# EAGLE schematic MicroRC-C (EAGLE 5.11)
BOM: EXCLUDE; CHECKED: K.OLINGER; DATABASE: ./BOM/MicroRC-PARTSDB.txt; DATE: 10/10/06; DRAWN: R.STARR; DRGNO: ED-3XX-01; PARTNO: *; PARTNUM: MF-SM030-2; REV: C

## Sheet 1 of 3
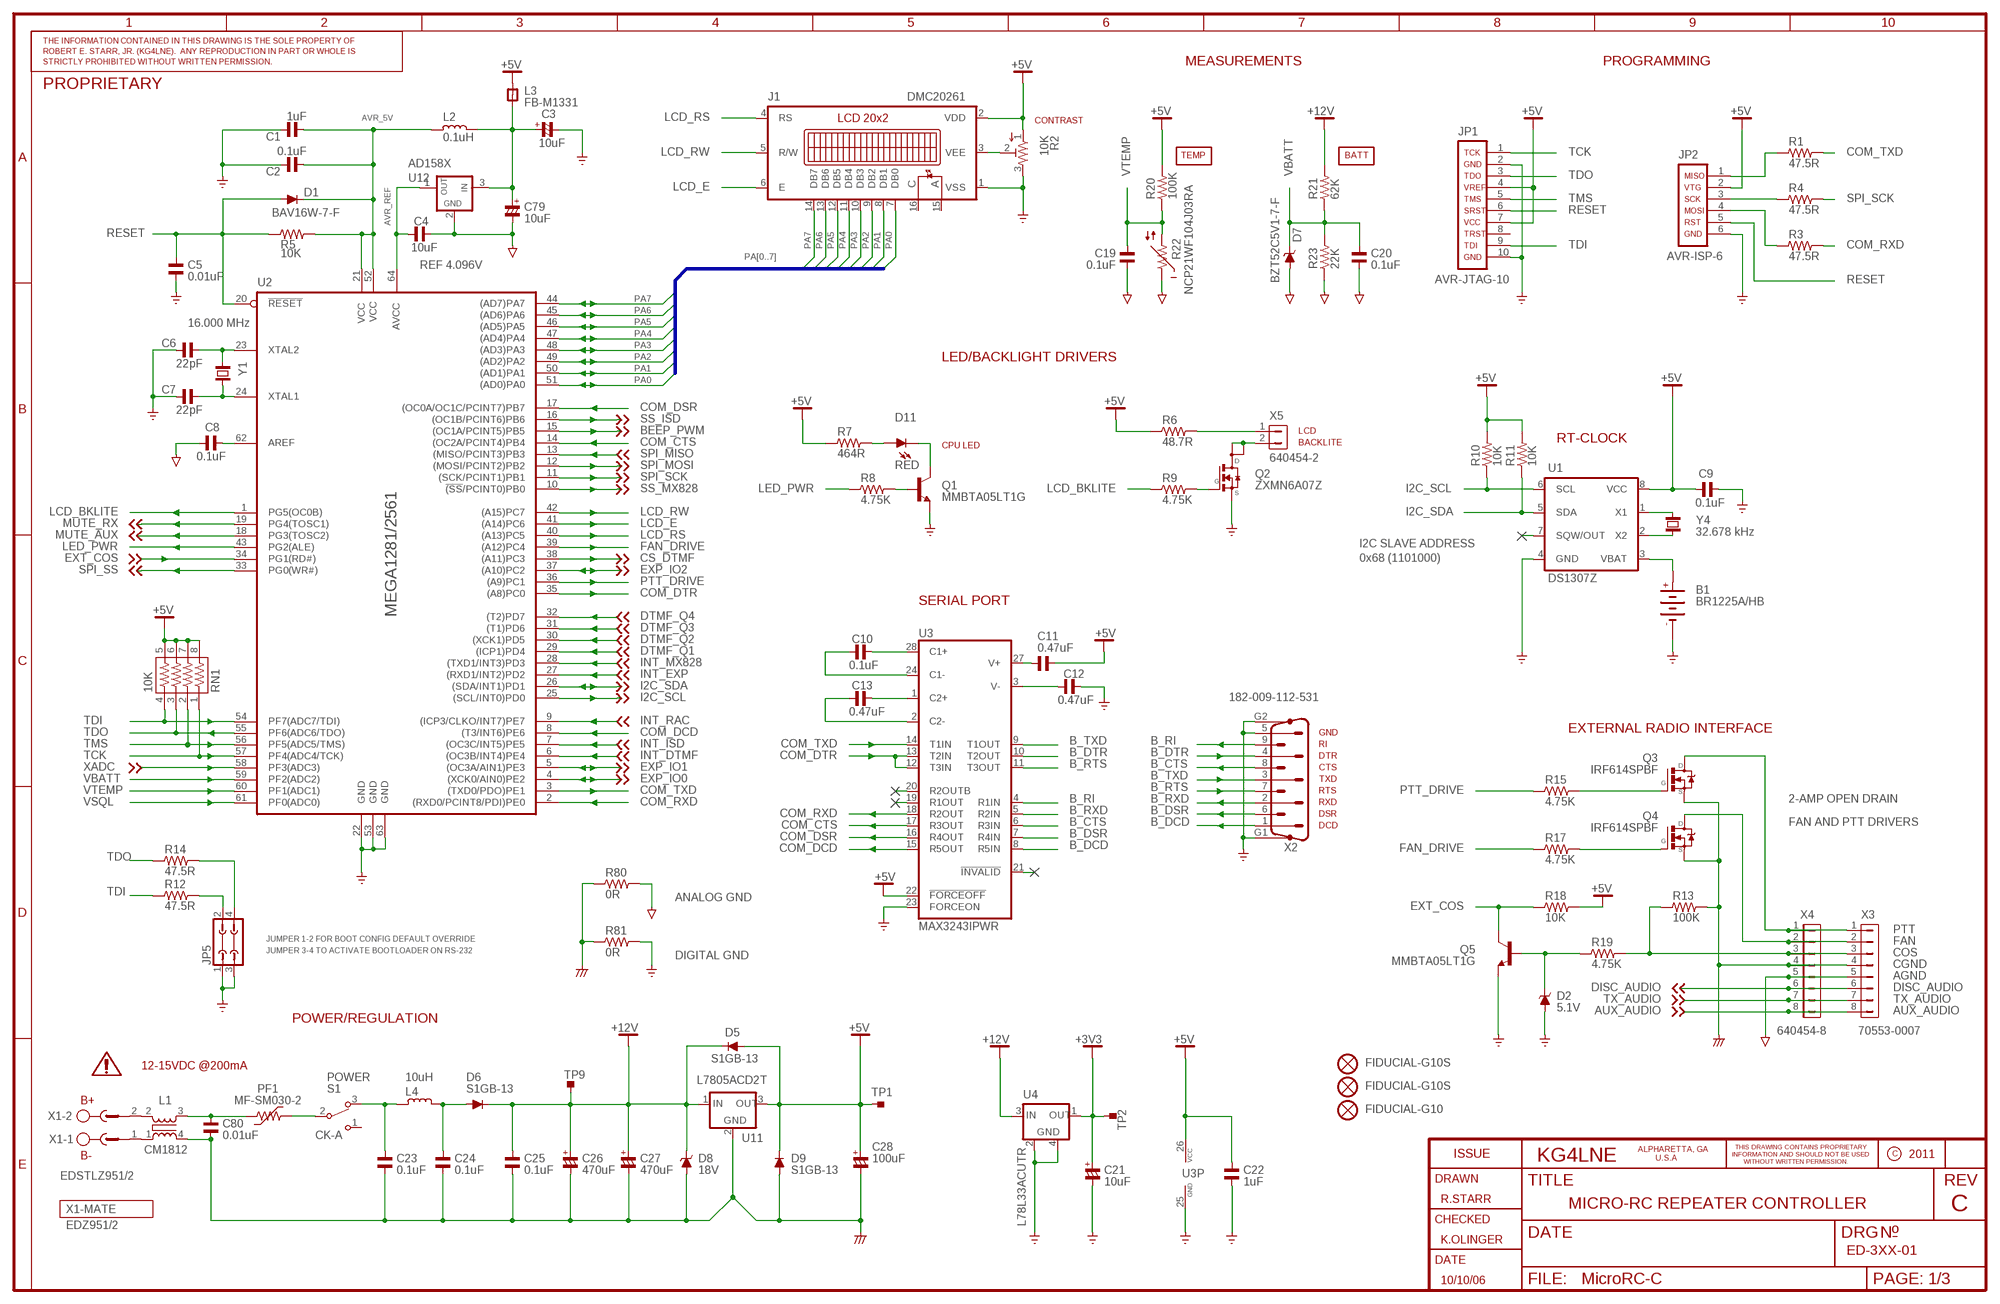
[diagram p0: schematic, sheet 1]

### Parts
B1  BR1225A/HB  BR1225  [BR1225]
C1  1uF  C_0805  [C0805]
C2  0.1uF  C_0805  [C0805]
C3  10uF  CP_3528  [C3528/T]
C4  10uF  C_0805  [C0805]
C5  0.01uF  C_0805  [C0805]
C6  22pF  C_0805  [C0805]
C7  22pF  C_0805  [C0805]
C8  0.1uF  C_0805  [C0805]
C9  0.1uF  C_0805  [C0805]
C10  0.1uF  C_0805  [C0805]
C11  0.47uF  C_0805  [C0805]
C12  0.47uF  C_0805  [C0805]
C13  0.47uF  C_0805  [C0805]
C19  0.1uF  C_0805  [C0805]
C20  0.1uF  C_0805  [C0805]
C21  10uF  CP_3528  [C3528/T]
C22  1uF  C_0805  [C0805]
C23  0.1uF  C_1206  [C1206]
C24  0.1uF  C_1206  [C1206]
C25  0.1uF  C_1206  [C1206]
C26  470uF  CP_SV-G  [CSV-G]
C27  470uF  CP_SV-G  [CSV-G]
C28  100uF  CP_SV-E/F  [CSV-E/F]
C79  10uF  CP_3528  [C3528/T]
C80  0.01uF  C_1206  [C1206]
D1  BAV16W-7-F  DIODE-SOD123  [SOD123]
D2  5.1V  ZENER-DIODESOD123  [SOD123]
D5  S1GB-13  [SMB]
D6  S1GB-13  [SMB]
D7  BZT52C5V1-7-F  ZENER-DIODESOD123  [SOD123]
D8  18V  ZENER-DIODESMB  [SMB]
D9  S1GB-13  [SMB]
D11  RED  LED535XX  [LED535]
FIDUCIAL1  FIDUCIAL-G10S  [G10S]
FIDUCIAL2  FIDUCIAL-G10S  [G10S]
FIDUCIAL3  FIDUCIAL-G10  [G10]
J1  DMC20261  [DMC20261]
JP1  AVR-JTAG-10  [AVR-JTAG-10]
JP2  AVR-ISP-6  [AVR-ISP-6]
JP5  JP2Q  [JP2Q]
L1  CM1812  [CM1812]
L2  0.1uH  L_1206  [L1206]
L3  FB-M1331  FB_1206  [L1206]
L4  10uH  L-PM3308  [PM-13]
PF1  MF-SM030-2  POLYSWITCH-SMD-7555  [SMD-7555]
Q1  MMBTA05LT1G  MMBTA05  [SOT23]
Q2  ZXMN6A07Z  [SOT89]
Q3  IRF614SPBF  IRF614  [D2PAK]
Q4  IRF614SPBF  IRF614  [D2PAK]
Q5  MMBTA05LT1G  MMBTA05  [SOT23]
R1  47.5R  R_0805  [R0805]
R2  10K  TRIM_EU-EVM-L4G  [EVM-L4G]
R3  47.5R  R_0805  [R0805]
R4  47.5R  R_0805  [R0805]
R5  10K  R_0805  [R0805]
R6  48.7R  R_2010  [R2010]
R7  464R  R_1210  [R1210]
R8  4.75K  R_0805  [R0805]
R9  4.75K  R_0805  [R0805]
R10  10K  R_0805  [R0805]
R11  10K  R_0805  [R0805]
R12  47.5R  R_0805  [R0805]
R13  100K  R_0805  [R0805]
R14  47.5R  R_0805  [R0805]
R15  4.75K  R_0805  [R0805]
R17  4.75K  R_0805  [R0805]
R18  10K  R_0805  [R0805]
R19  4.75K  R_0805  [R0805]
R20  100K  R_0805  [R0805]
R21  62K  R_0805  [R0805]
R22  NCP21WF104J03RA  NCP-0805  [R0805]
R23  22K  R_0805  [R0805]
R80  0R  R_0805  [R0805]
R81  0R  R_0805  [R0805]
RN1  10K  744-8  [744-8]
S1  CK-A  [CK-A]
TP1  TPTP10SQ  [TP10SQ]
TP2  TPTP10SQ  [TP10SQ]
TP9  TPTP10SQ  [TP10SQ]
U1  DS1307Z  [SO08]
U2  MEGA1281/2561  [TQFP64-AEB]
U3  MAX3243IPWR  MAX3243PW  [TSSOP28]
U4  L78L33ACUTR  L78LXXCU/BU  [SOT89-4]
U11  L7805ACD2T  L78XXD2T  [D2PAK]
U12  AD158X  [SOT23]
X1  EDSTLZ951/2  EDSTLZ-2-951  [951-2]
X2  182-009-112-531  NC182M9-VS  [NC182M9]
X3  70553-0007  HDR-1X8-70553-?  [70553-08]
X4  640454-8  MTA08-100  [MTA08-100]
X5  640454-2  HDR-1X2-MTA-100  [MTA-100-2V]
Y1  16.000 MHz  CRYTALTC38H  [TC38H]
Y4  32.678 kHz  CRYTALTC26H  [TC26H]

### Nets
+3V3: C21.+ TP2.TP U4.1(OUT) ; also sheet 2
+5V: C9.1 C11.1 C22.1 C28.+ D5.A D9.C J1.2(VDD) JP1.4 JP1.7 JP2.2 L3.2 R2.1 R6.1 R7.1 R10.2 R11.2 R18.2 R20.2 RN1.5 RN1.6 RN1.7 RN1.8 TP1.TP U1.8(VCC) U3.22(!FORCEOFF!) U3.26(VCC) U11.3(OUT) ; also sheet 2
+12V: C25.1 C26.+ C27.+ D5.C D6.C D8.C R21.2 TP9.TP U4.3(IN) U11.1(IN) ; also sheet 2
AGND: C4.1 C8.2 C19.2 C20.2 C79.- D7.A R22.1 R23.1 R80.2 U12.2(GND) X3.5 X4.5 ; supply symbol labelled AGND_ ; also sheet 2
AUX_AUDIO: X3.8 X4.8 ; also sheet 2
AVR_5V: C1.1 C2.1 D1.C L2.2 R5.2 U2.21(VCC) U2.52(VCC1)
AVR_REF: C4.2 U2.64(AVCC) U12.1(OUT)
B_CTS: U3.6(R3IN) X2.8
B_DCD: U3.8(R5IN) X2.1
B_DSR: U3.7(R4IN) X2.6
B_DTR: U3.10(T2OUT) X2.4
B_RI: U3.4(R1IN) X2.9
B_RTS: U3.11(T3OUT) X2.7
B_RXD: U3.5(R2IN) X2.2
B_TXD: U3.9(T1OUT) X2.3
BEEP_PWM: U2.15((OC1A/PCINT5)PB5) ; also sheet 2
CGND: C23.2 C24.2 C25.2 C26.- C27.- C28.- C80.2 D8.A D9.A L1.4 Q3.3(S) Q4.3(S) R13.2 R80.1 R81.1 U11.2(GND) X3.4 X4.4 ; supply symbol labelled CGND_
COM_CTS: U2.14((OC2A/PCINT4)PB4) U3.17(R3OUT)
COM_DCD: U2.8((T3/INT6)PE6) U3.15(R5OUT)
COM_DSR: U2.17((OC0A/OC1C/PCINT7)PB7) U3.16(R4OUT)
COM_DTR: U2.35((A8)PC0) U3.12(T3IN) U3.13(T2IN)
COM_RXD: R3.2 U2.2((RXD0/PCINT8/PDI)PE0) U3.18(R2OUT)
COM_TXD: R1.2 U2.3((TXD0/PDO)PE1) U3.14(T1IN)
COS: R13.1 R19.2 X3.3 X4.3
CS_DTMF: U2.38((A11)PC3) ; also sheet 2
DISC_AUDIO: X3.6 X4.6 ; also sheet 2
DTMF_Q1: U2.29((ICP1)PD4) ; also sheet 2
DTMF_Q2: U2.30((XCK1)PD5) ; also sheet 2
DTMF_Q3: U2.31((T1)PD6) ; also sheet 2
DTMF_Q4: U2.32((T2)PD7) ; also sheet 2
EXP_IO0: U2.4((XCK0/AIN0)PE2) ; also sheet 2
EXP_IO1: U2.5((OC3A/AIN1)PE3) ; also sheet 2
EXP_IO2: U2.37((A10)PC2) ; also sheet 2
EXT_COS: Q5.3(C) R18.1 U2.34(PG1(RD#))
FAN: Q4.2(D) X3.2 X4.2
FAN_DRIVE: R17.1 U2.39((A12)PC4)
GND: B1.- C1.2 C2.2 C3.- C5.2 C6.2 C7.2 C9.2 C12.1 C21.- C22.2 D2.A J1.1(VSS) JP1.2 JP1.10 JP2.6 JP5.1 JP5.3 Q1.2(E) Q2.3(S) Q5.2(E) R2.3 R81.2 U1.4(GND) U2.22(GND) U2.53(GND1) U2.63(GND2) U3.23(FORCEON) U3.25(GND) U4.2(GND) U4.4(GND1) X2.5 X2.G1 X2.G2 ; supply symbol labelled GND_ ; also sheet 2
I2C_SCL: R10.1 U1.6(SCL) U2.25((SCL/INT0)PD0) ; also sheet 2
I2C_SDA: R11.1 U1.5(SDA) U2.26((SDA/INT1)PD1) ; also sheet 2
INT_DTMF: U2.6((OC3B/INT4)PE4) ; also sheet 2
INT_EXP: U2.27((RXD1/INT2)PD2) ; also sheet 2
INT_ISD: U2.7((OC3C/INT5)PE5) ; also sheet 2
INT_MX828: U2.28((TXD1/INT3)PD3) ; also sheet 2
INT_RAC: U2.9((ICP3/CLKO/INT7)PE7) ; also sheet 2
LCD_BKLITE: R9.1 U2.1(PG5(OC0B))
LCD_E: J1.6(E) U2.41((A14)PC6)
LCD_RS: J1.4(RS) U2.40((A13)PC5)
LCD_RW: J1.5(R/W) U2.42((A15)PC7)
LED_PWR: R8.1 U2.43(PG2(ALE))
MUTE_AUX: U2.18(PG3(TOSC2)) ; also sheet 2
MUTE_RX: U2.19(PG4(TOSC1)) ; also sheet 2
N$1: L1.1 X1.1
N$2: C8.1 U2.62(AREF)
N$9: JP5.2 R12.2
N$13: C23.1 L4.1 S1.3(O)
N$14: L1.2 X1.2
N$19: C24.1 D6.A L4.2
N$20: U1.1(X1) Y4.2
N$21: U1.2(X2) Y4.1
N$30: C7.1 U2.24(XTAL1) Y1.1
N$31: JP5.4 R14.2
N$34: C12.2 U3.3(V-)
N$36: C11.2 U3.27(V+)
N$38: C6.1 U2.23(XTAL2) Y1.2
N$39: C13.1 U3.1(C2+)
N$44: C10.1 U3.28(C1+)
N$45: C13.2 U3.2(C2-)
N$46: C10.2 U3.24(C1-)
N$63: B1.+ U1.3(VBAT)
N$66: Q3.1(G) R15.2
N$67: Q2.1(G) R9.2
N$68: Q2.2(D) Q2.4(D2) X5.2
N$69: R6.2 X5.1
N$76: D2.C Q5.1(B) R19.1
N$78: PF1.2 S1.2(P)
N$79: Q4.1(G) R17.2
N$81: C80.1 L1.3 PF1.1
N$86: C3.+ C79.+ L2.1 L3.1 U12.3(IN)
N$90: D11.K(C) Q1.3(C)
N$91: D11.A R7.2
N$92: Q1.1(B) R8.2
N$105: JP2.1 R1.1
N$107: JP2.3 R4.1
N$108: JP2.4 R3.1
PA0: J1.7(DB0) U2.51((AD0)PA0)
PA1: J1.8(DB1) U2.50((AD1)PA1)
PA2: J1.9(DB2) U2.49((AD2)PA2)
PA3: J1.10(DB3) U2.48((AD3)PA3)
PA4: J1.11(DB4) U2.47((AD4)PA4)
PA5: J1.12(DB5) U2.46((AD5)PA5)
PA6: J1.13(DB6) U2.45((AD6)PA6)
PA7: J1.14(DB7) U2.44((AD7)PA7)
PTT: Q3.2(D) X3.1 X4.1
PTT_DRIVE: R15.1 U2.36((A9)PC1)
RESET: C5.1 D1.A JP1.6 JP2.5 R5.1 U2.20(!RESET!)
SPI_MISO: U2.13((MISO/PCINT3)PB3) ; also sheet 2
SPI_MOSI: U2.12((MOSI/PCINT2)PB2) ; also sheet 2
SPI_SCK: R4.2 U2.11((SCK/PCINT1)PB1) ; also sheet 2
SPI_SS: U2.33(PG0(WR#)) ; also sheet 2
SS_ISD: U2.16((OC1B/PCINT6)PB6) ; also sheet 2
SS_MX828: U2.10(!(SS!/PCINT0)PB0) ; also sheet 2
TCK: JP1.1 RN1.1 U2.57(PF4(ADC4/TCK))
TDI: JP1.9 R12.1 RN1.4 U2.54(PF7(ADC7/TDI))
TDO: JP1.3 R14.1 RN1.3 U2.55(PF6(ADC6/TDO))
TMS: JP1.5 RN1.2 U2.56(PF5(ADC5/TMS))
TX_AUDIO: X3.7 X4.7 ; also sheet 2
VBATT: C20.1 D7.C R21.1 R23.2 U2.59(PF2(ADC2))
VEE_LCD: J1.3(VEE) R2.2
VSQL: U2.61(PF0(ADC0)) ; also sheet 2
VTEMP: C19.1 R20.1 R22.2 U2.60(PF1(ADC1))
XADC: U2.58(PF3(ADC3)) ; also sheet 2
Unconnected: J1.15(A) J1.16(C) JP1.8 S1.1(S) U1.7(SQW/OUT) U3.19(R1OUT) U3.20(R2OUTB) U3.21(!INVALID!)

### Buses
PA[0..7]

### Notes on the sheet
- MEASUREMENTS | PROGRAMMING
- CONTRAST
- TEMP | BATT
- REF 4.096V
- LED/BACKLIGHT DRIVERS
- LCD
- RT-CLOCK
- BACKLITE
- CPU LED
- I2C SLAVE ADDRESS
- 0x68 (1101000)
- SERIAL PORT
- EXTERNAL RADIO INTERFACE
- GND
- RI
- DTR
- CTS
- TXD
- RTS
- 2-AMP OPEN DRAIN
- RXD
- DSR
- FAN AND PTT DRIVERS
- DCD
- ANALOG GND
- JUMPER 1-2 FOR BOOT CONFIG DEFAULT OVERRIDE
- JUMPER 3-4 TO ACTIVATE BOOTLOADER ON RS-232
- DIGITAL GND
- POWER/REGULATION
- 12-15VDC @200mA
- POWER
- B+
- B-
- MICRO-RC REPEATER CONTROLLER

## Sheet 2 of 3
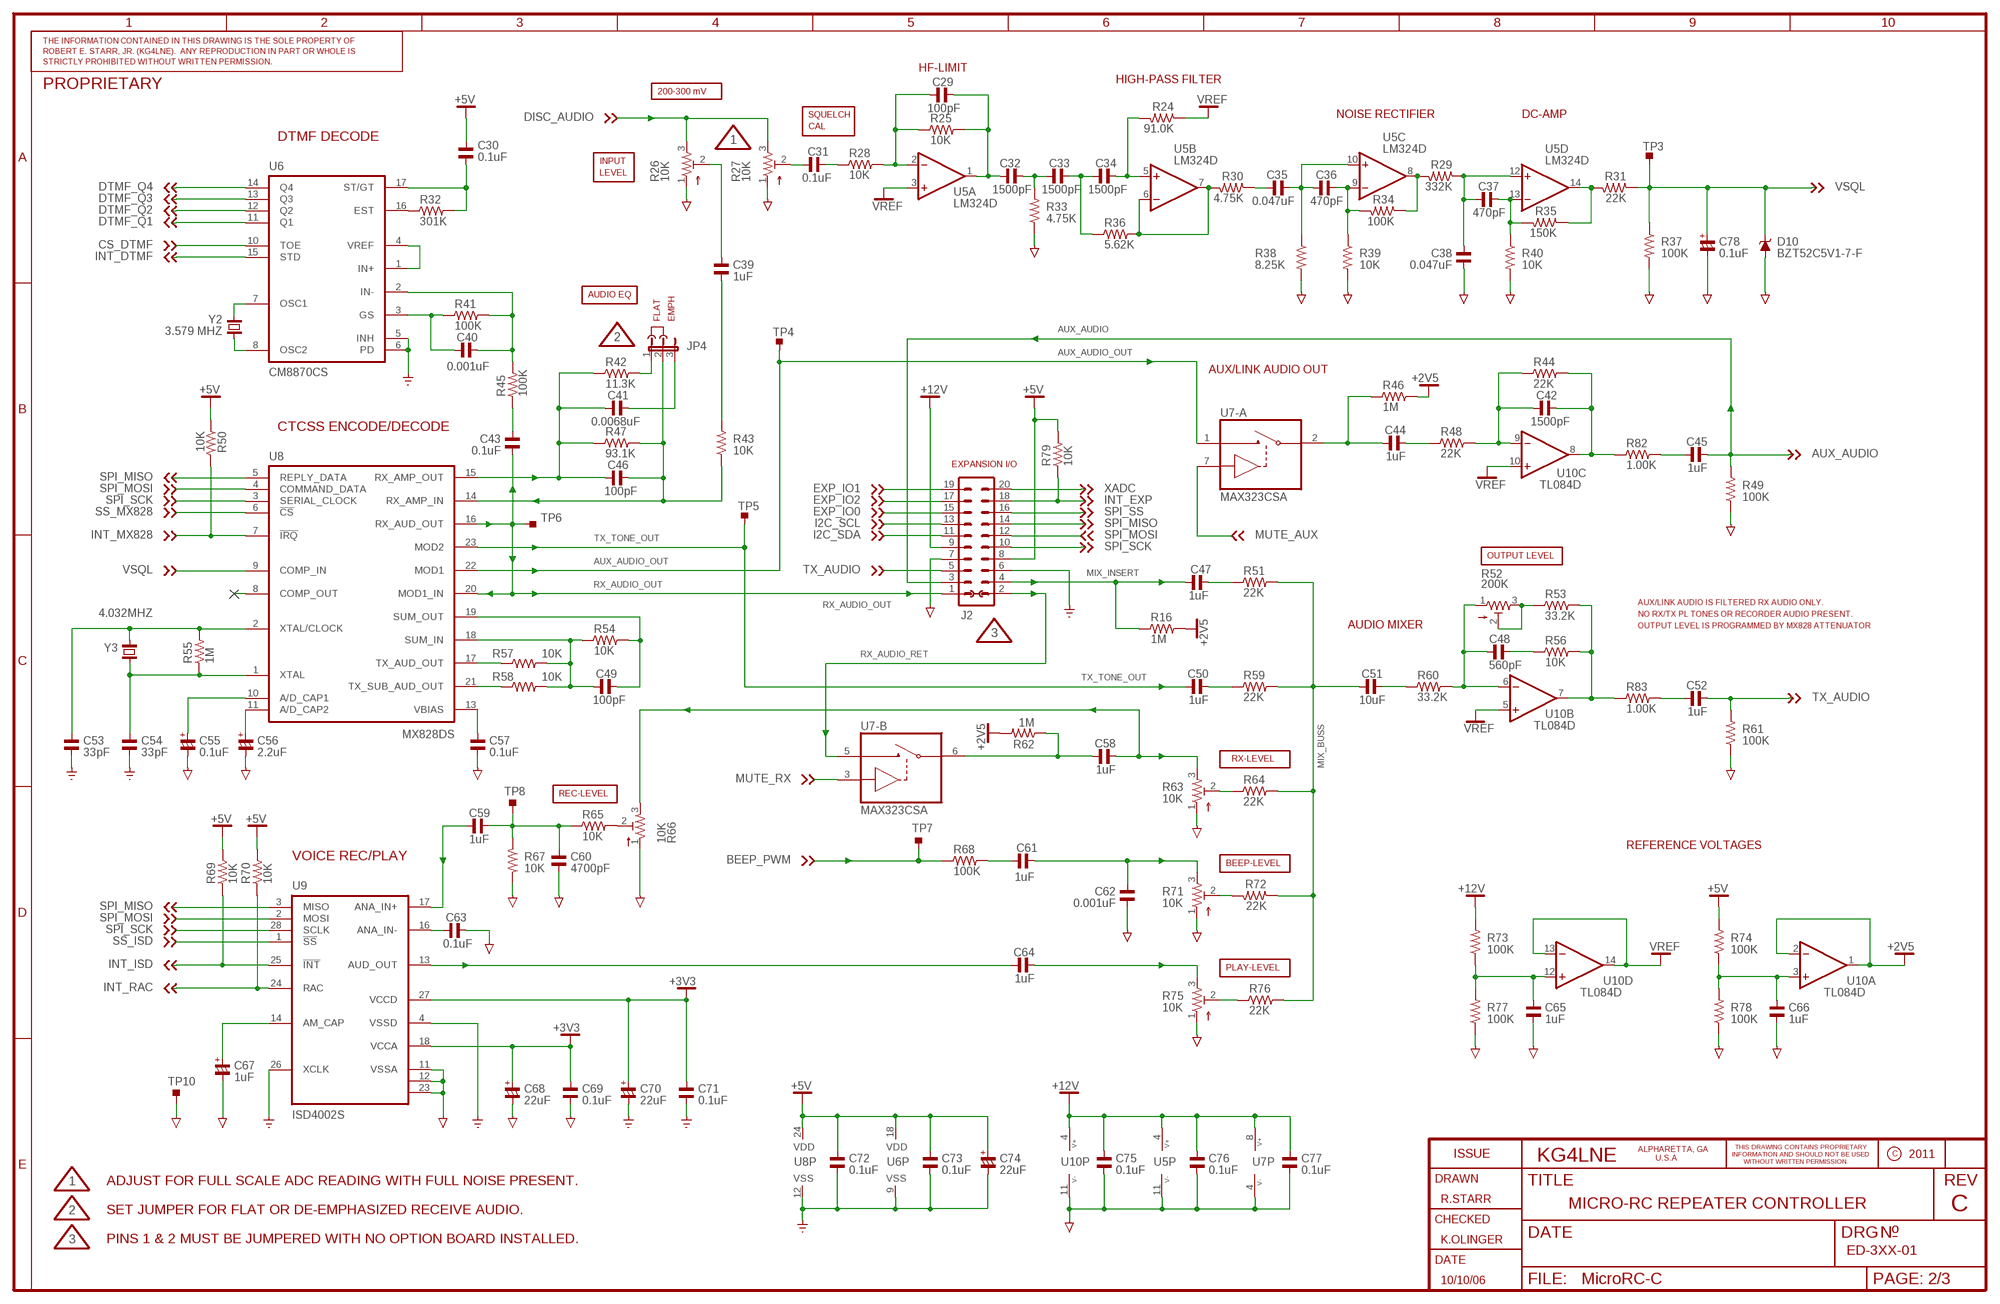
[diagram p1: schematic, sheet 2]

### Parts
C29  100pF  C_0805  [C0805]
C30  0.1uF  C_0805  [C0805]
C31  0.1uF  C_0805  [C0805]
C32  1500pF  C_0805  [C0805]
C33  1500pF  C_0805  [C0805]
C34  1500pF  C_0805  [C0805]
C35  0.047uF  C_0805  [C0805]
C36  470pF  C_0805  [C0805]
C37  470pF  C_0805  [C0805]
C38  0.047uF  C_0805  [C0805]
C39  1uF  C_0805  [C0805]
C40  0.001uF  C_0805  [C0805]
C41  0.0068uF  C_0805  [C0805]
C42  1500pF  C_0805  [C0805]
C43  0.1uF  C_0805  [C0805]
C44  1uF  C_0805  [C0805]
C45  1uF  C_0805  [C0805]
C46  100pF  C_0805  [C0805]
C47  1uF  C_0805  [C0805]
C48  560pF  C_0805  [C0805]
C49  100pF  C_0805  [C0805]
C50  1uF  C_0805  [C0805]
C51  10uF  C_0805  [C0805]
C52  1uF  C_0805  [C0805]
C53  33pF  C_0805  [C0805]
C54  33pF  C_0805  [C0805]
C55  0.1uF  CP_3216  [C3216/T]
C56  2.2uF  CP_3216  [C3216/T]
C57  0.1uF  C_0805  [C0805]
C58  1uF  C_0805  [C0805]
C59  1uF  C_0805  [C0805]
C60  4700pF  C_0805  [C0805]
C61  1uF  C_0805  [C0805]
C62  0.001uF  C_0805  [C0805]
C63  0.1uF  C_0805  [C0805]
C64  1uF  C_0805  [C0805]
C65  1uF  C_0805  [C0805]
C66  1uF  C_0805  [C0805]
C67  1uF  CP_3216  [C3216/T]
C68  22uF  CP_3528  [C3528/T]
C69  0.1uF  C_0805  [C0805]
C70  22uF  CP_3528  [C3528/T]
C71  0.1uF  C_0805  [C0805]
C72  0.1uF  C_0805  [C0805]
C73  0.1uF  C_0805  [C0805]
C74  22uF  CP_3528  [C3528/T]
C75  0.1uF  C_0805  [C0805]
C76  0.1uF  C_0805  [C0805]
C77  0.1uF  C_0805  [C0805]
C78  0.1uF  CP_3216  [C3216/T]
D10  BZT52C5V1-7-F  ZENER-DIODESOD123  [SOD123]
J2  MA10-2  [MA10-2]
JP4  JP2E  [JP2]
R16  1M  R_0805  [R0805]
R24  91.0K  R_0805  [R0805]
R25  10K  R_0805  [R0805]
R26  10K  TRIM_EU-EVME-SIDE  [EVME-SIDE]
R27  10K  TRIM_EU-EVME-SIDE  [EVME-SIDE]
R28  10K  R_0805  [R0805]
R29  332K  R_0805  [R0805]
R30  4.75K  R_0805  [R0805]
R31  22K  R_0805  [R0805]
R32  301K  R_0805  [R0805]
R33  4.75K  R_0805  [R0805]
R34  100K  R_0805  [R0805]
R35  150K  R_0805  [R0805]
R36  5.62K  R_0805  [R0805]
R37  100K  R_0805  [R0805]
R38  8.25K  R_0805  [R0805]
R39  10K  R_0805  [R0805]
R40  10K  R_0805  [R0805]
R41  100K  R_0805  [R0805]
R42  11.3K  R_0805  [R0805]
R43  10K  R_0805  [R0805]
R44  22K  R_0805  [R0805]
R45  100K  R_0805  [R0805]
R46  1M  R_0805  [R0805]
R47  93.1K  R_0805  [R0805]
R48  22K  R_0805  [R0805]
R49  100K  R_0805  [R0805]
R50  10K  R_0805  [R0805]
R51  22K  R_0805  [R0805]
R52  200K  TRIM_EU-EVME-SIDE  [EVME-SIDE]
R53  33.2K  R_0805  [R0805]
R54  10K  R_0805  [R0805]
R55  1M  R_0805  [R0805]
R56  10K  R_0805  [R0805]
R57  10K  R_0805  [R0805]
R58  10K  R_0805  [R0805]
R59  22K  R_0805  [R0805]
R60  33.2K  R_0805  [R0805]
R61  100K  R_0805  [R0805]
R62  1M  R_0805  [R0805]
R63  10K  TRIM_EU-EVME-SIDE  [EVME-SIDE]
R64  22K  R_0805  [R0805]
R65  10K  R_0805  [R0805]
R66  10K  TRIM_EU-EVM-L4G  [EVM-L4G]
R67  10K  R_0805  [R0805]
R68  100K  R_0805  [R0805]
R69  10K  R_0805  [R0805]
R70  10K  R_0805  [R0805]
R71  10K  TRIM_EU-EVME-SIDE  [EVME-SIDE]
R72  22K  R_0805  [R0805]
R73  100K  R_0805  [R0805]
R74  100K  R_0805  [R0805]
R75  10K  TRIM_EU-EVME-SIDE  [EVME-SIDE]
R76  22K  R_0805  [R0805]
R77  100K  R_0805  [R0805]
R78  100K  R_0805  [R0805]
R79  10K  R_0805  [R0805]
R82  1.00K  R_0805  [R0805]
R83  1.00K  R_0805  [R0805]
TP3  TPTP10SQ  [TP10SQ]
TP4  TPTP10SQ  [TP10SQ]
TP5  TPTP10SQ  [TP10SQ]
TP6  TPTP10SQ  [TP10SQ]
TP7  TPTP10SQ  [TP10SQ]
TP8  TPS-SMD-10SN  [SMD-10SN]
TP10  TPS-SMD-10SN  [SMD-10SN]
U5  LM324D  [SO14]
U6  CM8870CS  [SO18W]
U7  MAX323CSA  [SO08]
U8  MX828DS  [SSOP24]
U9  ISD4002S  [SO28W]
U10  TL084D  [SO14]
Y2  3.579 MHZ  CRYTALTC310H  [TC310H]
Y3  4.032MHZ  CRYTALSM49  [SM49]

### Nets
+2V5: R16.2 R46.2 R62.2 U10.1(A:OUT) U10.2(A:-IN)
+3V3: C68.+ C69.1 C70.+ C71.1 U9.18(VCCA) U9.27(VCCD) ; also sheet 1
+5V: C30.2 C72.1 C73.1 C74.+ J2.8 R50.1 R69.2 R70.2 R74.2 R79.2 U6.18(VDD) U8.24(P:VDD) ; also sheet 1
+12V: C75.1 C76.1 C77.1 J2.9 R73.2 U5.4(P:V+) U7.8(P:V+) U10.4(P:V+) ; also sheet 1
AGND: C38.1 C55.- C56.- C57.2 C60.2 C62.2 C63.1 C65.2 C66.2 C67.- C68.- C69.2 C75.2 C76.2 C77.2 C78.- D10.A J2.7 R26.1 R27.1 R33.1 R37.2 R38.2 R39.2 R40.2 R49.1 R61.1 R63.1 R66.1 R67.2 R71.1 R75.1 R77.1 R78.1 TP10.TP U5.11(P:V-) U7.4(P:V-) U9.11(VSSA) U9.12(VSSA) U9.23(VSSA) U10.11(P:V-) ; supply symbol labelled AGND_ ; also sheet 1
AUX_AUDIO: C45.2 J2.3 R49.2 ; also sheet 1
AUX_AUDIO_OUT: TP4.TP U7.1(-A:NO) U8.22(A:MOD1)
BEEP_PWM: R68.1 TP7.TP ; also sheet 1
CS_DTMF: U6.10(TOE) ; also sheet 1
DISC_AUDIO: R26.3 R27.3 ; also sheet 1
DTMF_Q1: U6.11(Q1) ; also sheet 1
DTMF_Q2: U6.12(Q2) ; also sheet 1
DTMF_Q3: U6.13(Q3) ; also sheet 1
DTMF_Q4: U6.14(Q4) ; also sheet 1
EXP_IO0: J2.15 ; also sheet 1
EXP_IO1: J2.19 ; also sheet 1
EXP_IO2: J2.17 ; also sheet 1
GND: C53.2 C54.2 C70.- C71.2 C72.2 C73.2 C74.- J2.6 U6.5(INH) U6.6(PD) U6.9(VSS) U8.12(P:VSS) U9.4(VSSD) U9.26(XCLK) ; supply symbol labelled GND_ ; also sheet 1
I2C_SCL: J2.13 ; also sheet 1
I2C_SDA: J2.11 ; also sheet 1
INT_DTMF: U6.15(STD) ; also sheet 1
INT_EXP: J2.18 R79.1 ; also sheet 1
INT_ISD: R69.1 U9.25(!INT!) ; also sheet 1
INT_MX828: R50.2 U8.7(A:!IRQ!) ; also sheet 1
INT_RAC: R70.1 U9.24(RAC) ; also sheet 1
MIX_BUSS: C51.1 R51.2 R59.2 R64.2 R72.1 R76.2
MIX_INSERT: C47.1 J2.4 R16.1
MUTE_AUX: U7.7(-A:IN) ; also sheet 1
MUTE_RX: U7.3(-B:IN) ; also sheet 1
N$3: C45.1 R82.2
N$4: C39.2 R26.2
N$5: C58.1 R62.1 U7.6(-B:COM)
N$6: R63.2 R64.1
N$7: R65.2 R66.2
N$8: C63.2 U9.16(ANA_IN-)
N$10: C56.+ U8.11(A:A/D_CAP2)
N$11: C52.1 R83.2
N$12: JP4.1 R42.2
N$15: C59.1 C60.1 R65.1 R67.1 TP8.TP
N$16: U6.7(OSC1) Y2.2
N$17: U6.8(OSC2) Y2.1
N$18: U6.1(IN+) U6.4(VREF)
N$22: C61.1 R68.2
N$23: R75.2 R76.1
N$24: C65.1 R73.1 R77.2 U10.12(D:+IN)
N$25: C64.2 R75.3
N$26: C40.2 R41.2 R45.2 U6.2(IN-)
N$27: C41.2 JP4.3
N$28: C40.1 R41.1 U6.3(GS)
N$29: C30.1 R32.2 U6.17(ST/GT)
N$32: R32.1 U6.16(EST)
N$33: C59.2 U9.17(ANA_IN+)
N$35: C44.2 R48.1
N$37: C64.1 U9.13(AUD_OUT)
N$40: C43.2 R45.1
N$41: C55.+ U8.10(A:A/D_CAP1)
N$42: C48.2 R56.1
N$43: R30.2 R36.2 U5.6(B:-IN) U5.7(B:OUT)
N$47: C31.1 R27.2
N$48: C44.1 R46.1 U7.2(-A:COM)
N$49: C61.2 C62.1 R71.3
N$50: R71.2 R72.2
N$52: C53.1 R55.2 U8.2(A:XTAL/CLOCK) Y3.1
N$53: C54.1 R55.1 U8.1(A:XTAL) Y3.2
N$54: C49.2 R54.2 U8.19(A:SUM_OUT)
N$55: R53.2 R56.2 R83.1 U10.7(B:OUT)
N$56: C39.1 R43.2
N$57: C46.2 JP4.2 R43.1 R47.2 U8.14(A:RX_AMP_IN)
N$58: C57.1 U8.13(A:VBIAS)
N$59: C41.1 C46.1 R42.1 R47.1 U8.15(A:RX_AMP_OUT)
N$60: C48.1 R52.1 R60.2 U10.6(B:-IN)
N$61: C58.2 R63.3 R66.3
N$62: C50.2 R59.1
N$64: C32.2 C33.1 R33.2
N$70: R29.2 R34.1 U5.8(C:OUT)
N$72: C36.2 R34.2 R39.1 U5.9(C:-IN)
N$73: R57.1 U8.17(A:TX_AUD_OUT)
N$77: C35.1 R30.1
N$80: R58.1 U8.21(A:TX_SUB_AUD_OUT)
N$82: C34.2 R24.2 U5.5(B:+IN)
N$83: R52.2 R52.3 R53.1
N$84: C67.+ U9.14(AM_CAP)
N$85: C42.1 R44.1 R48.2 U10.9(C:-IN)
N$87: C42.2 R44.2 R82.1 U10.8(C:OUT)
N$88: C33.2 C34.1 R36.1
N$89: C49.1 R54.1 R57.2 R58.2 U8.18(A:SUM_IN)
N$93: C47.2 R51.1
N$94: C29.2 C32.1 R25.2 U5.1(A:OUT)
N$95: C35.2 C36.1 R38.1 U5.10(C:+IN)
N$96: C37.1 C38.2 R29.1 U5.12(D:+IN)
N$98: C29.1 R25.1 R28.2 U5.2(A:-IN)
N$99: C31.2 R28.1
N$102: C37.2 R35.2 R40.1 U5.13(D:-IN)
N$106: C51.2 R60.1
N$109: C66.1 R74.1 R78.2 U10.3(A:+IN)
N$111: R31.2 R35.1 U5.14(D:OUT)
RX_AUDIO_OUT: C43.1 J2.1 TP6.TP U8.16(A:RX_AUD_OUT) U8.20(A:MOD1_IN)
RX_AUDIO_RET: J2.2 U7.5(-B:NO)
SPI_MISO: J2.14 U8.5(A:REPLY_DATA) U9.3(MISO) ; also sheet 1
SPI_MOSI: J2.12 U8.4(A:COMMAND_DATA) U9.2(MOSI) ; also sheet 1
SPI_SCK: J2.10 U8.3(A:SERIAL_CLOCK) U9.28(SCLK) ; also sheet 1
SPI_SS: J2.16 ; also sheet 1
SS_ISD: U9.1(!SS!) ; also sheet 1
SS_MX828: U8.6(A:!CS!) ; also sheet 1
TX_AUDIO: C52.2 J2.5 R61.2 ; also sheet 1
TX_TONE_OUT: C50.1 TP5.TP U8.23(A:MOD2)
VREF: R24.1 U5.3(A:+IN) U10.5(B:+IN) U10.10(C:+IN) U10.13(D:-IN) U10.14(D:OUT)
VSQL: C78.+ D10.C R31.1 R37.1 TP3.TP U8.9(A:COMP_IN) ; also sheet 1
XADC: J2.20 ; also sheet 1
Unconnected: U8.8(A:COMP_OUT)

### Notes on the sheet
- HF-LIMIT
- HIGH-PASS FILTER
- 200-300 mV
- SQUELCH | NOISE RECTIFIER | DC-AMP
- CAL
- DTMF DECODE
- INPUT
- LEVEL
- AUDIO EQ
- FLAT | EMPH
- AUX/LINK AUDIO OUT
- CTCSS ENCODE/DECODE
- EXPANSION I/O
- OUTPUT LEVEL
- AUX/LINK AUDIO IS FILTERED RX AUDIO ONLY.
- NO RX/TX PL TONES OR RECORDER AUDIO PRESENT.
- AUDIO MIXER | OUTPUT LEVEL IS PROGRAMMED BY MX828 ATTENUATOR
- RX-LEVEL
- REC-LEVEL
- REFERENCE VOLTAGES
- VOICE REC/PLAY
- BEEP-LEVEL
- PLAY-LEVEL
- ADJUST FOR FULL SCALE ADC READING WITH FULL NOISE PRESENT.
- MICRO-RC REPEATER CONTROLLER
- SET JUMPER FOR FLAT OR DE-EMPHASIZED RECEIVE AUDIO.
- PINS 1 & 2 MUST BE JUMPERED WITH NO OPTION BOARD INSTALLED.

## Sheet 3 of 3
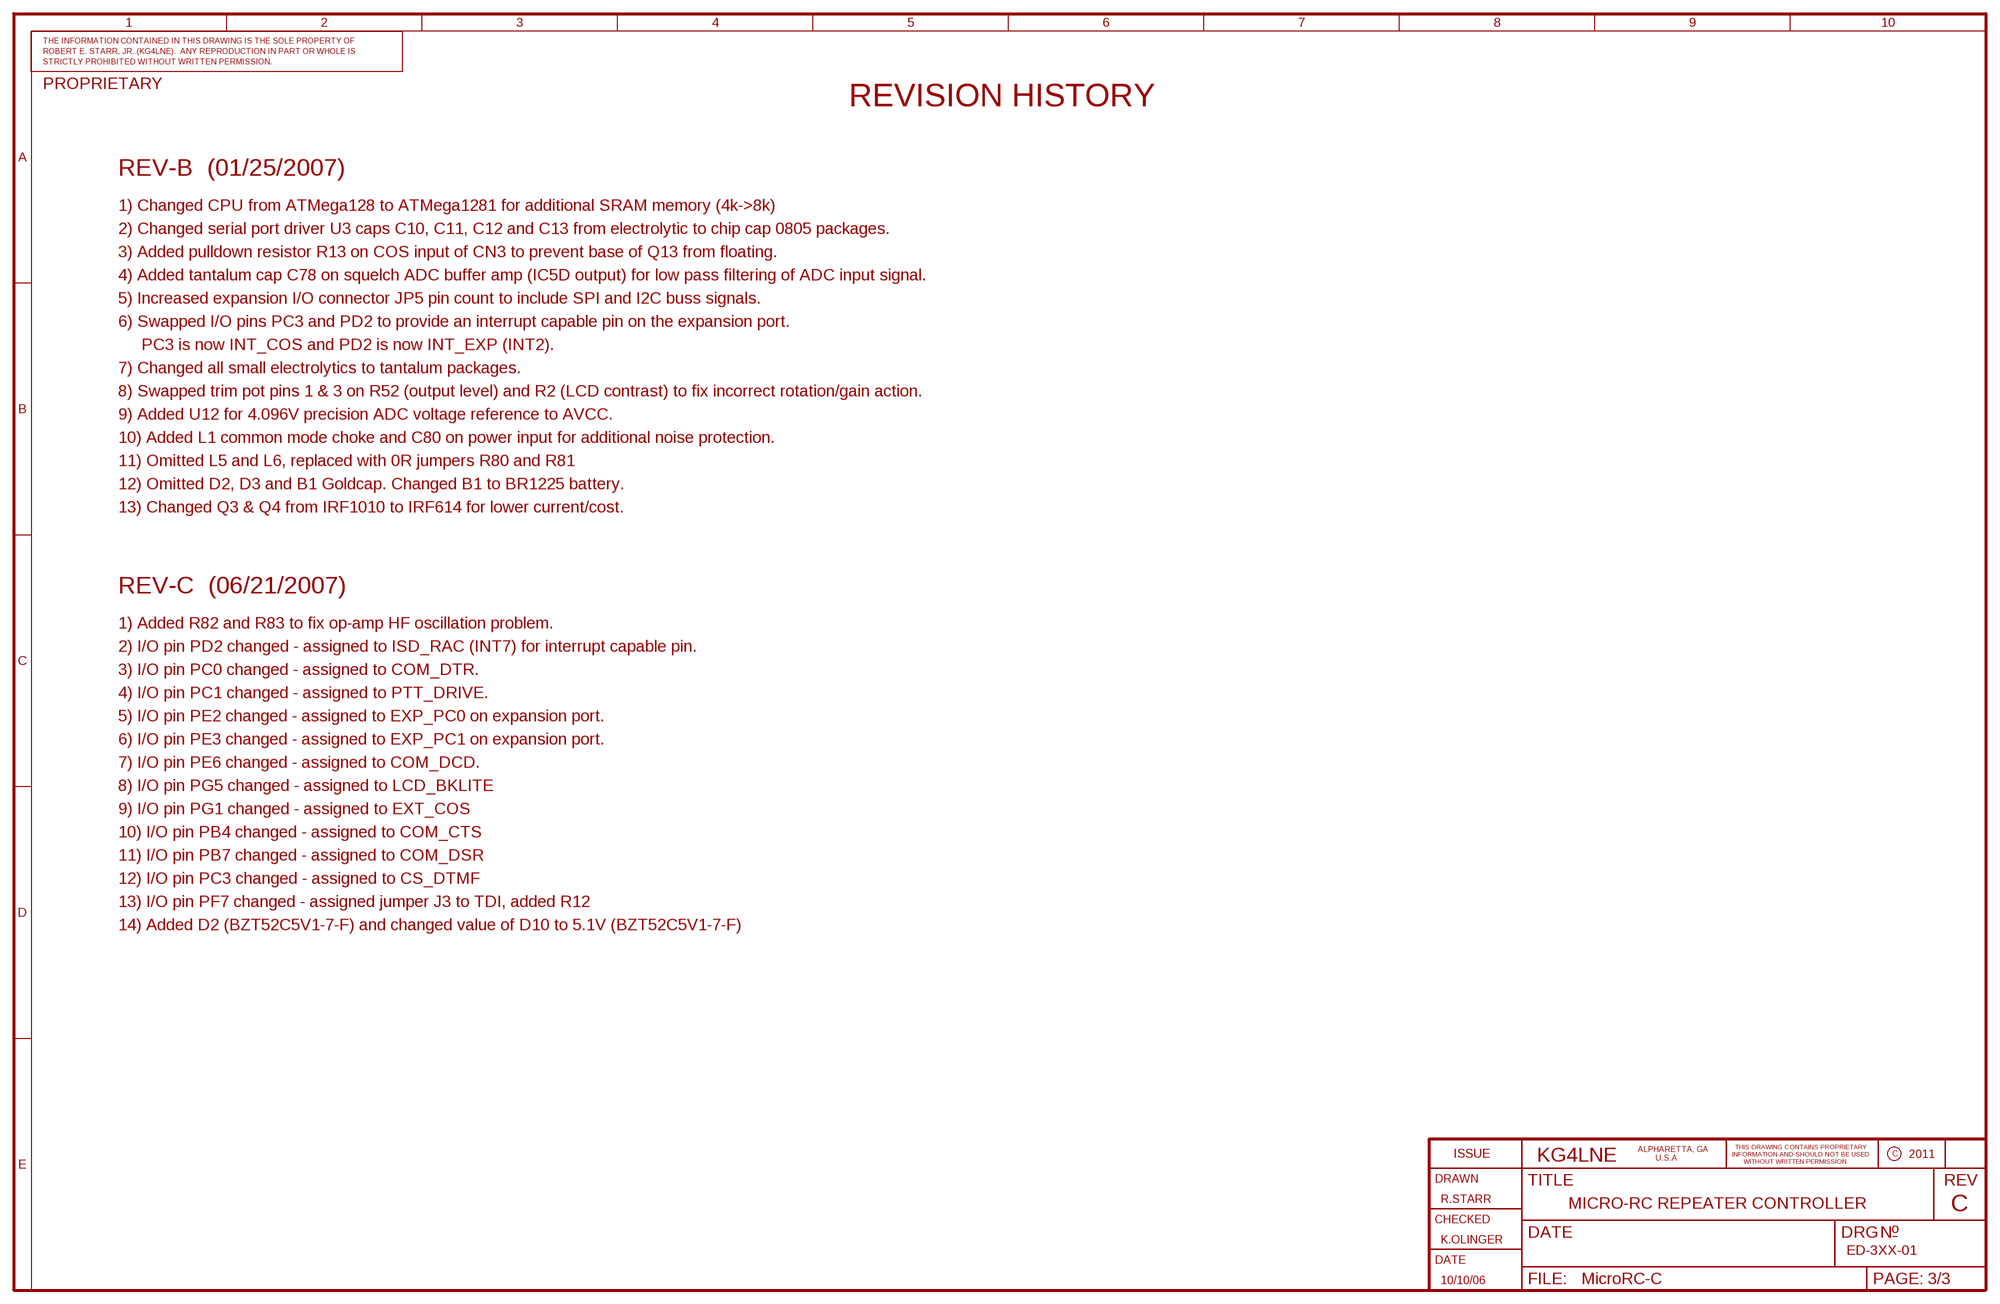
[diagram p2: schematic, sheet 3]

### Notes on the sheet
- REVISION HISTORY
- REV-B  (01/25/2007)
- 1) Changed CPU from ATMega128 to ATMega1281 for additional SRAM memory (4k->8k)
- 2) Changed serial port driver U3 caps C10, C11, C12 and C13 from electrolytic to chip cap 0805 packages.
- 3) Added pulldown resistor R13 on COS input of CN3 to prevent base of Q13 from floating.
- 4) Added tantalum cap C78 on squelch ADC buffer amp (IC5D output) for low pass filtering of ADC input signal.
- 5) Increased expansion I/O connector JP5 pin count to include SPI and I2C buss signals.
- 6) Swapped I/O pins PC3 and PD2 to provide an interrupt capable pin on the expansion port.
- PC3 is now INT_COS and PD2 is now INT_EXP (INT2).
- 7) Changed all small electrolytics to tantalum packages.
- 8) Swapped trim pot pins 1 & 3 on R52 (output level) and R2 (LCD contrast) to fix incorrect rotation/gain action.
- 9) Added U12 for 4.096V precision ADC voltage reference to AVCC.
- 10) Added L1 common mode choke and C80 on power input for additional noise protection.
- 11) Omitted L5 and L6, replaced with 0R jumpers R80 and R81
- 12) Omitted D2, D3 and B1 Goldcap. Changed B1 to BR1225 battery.
- 13) Changed Q3 & Q4 from IRF1010 to IRF614 for lower current/cost.
- REV-C  (06/21/2007)
- 1) Added R82 and R83 to fix op-amp HF oscillation problem.
- 2) I/O pin PD2 changed - assigned to ISD_RAC (INT7) for interrupt capable pin.
- 3) I/O pin PC0 changed - assigned to COM_DTR.
- 4) I/O pin PC1 changed - assigned to PTT_DRIVE.
- 5) I/O pin PE2 changed - assigned to EXP_PC0 on expansion port.
- 6) I/O pin PE3 changed - assigned to EXP_PC1 on expansion port.
- 7) I/O pin PE6 changed - assigned to COM_DCD.
- 8) I/O pin PG5 changed - assigned to LCD_BKLITE
- 9) I/O pin PG1 changed - assigned to EXT_COS
- 10) I/O pin PB4 changed - assigned to COM_CTS
- 11) I/O pin PB7 changed - assigned to COM_DSR
- 12) I/O pin PC3 changed - assigned to CS_DTMF
- 13) I/O pin PF7 changed - assigned jumper J3 to TDI, added R12
- 14) Added D2 (BZT52C5V1-7-F) and changed value of D10 to 5.1V (BZT52C5V1-7-F)
- MICRO-RC REPEATER CONTROLLER

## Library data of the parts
B1 = battery:BR1225: LI BATTERY Panasonic
C1 C2 C4-C13 C19 C20 C22-C25 C29-C54 C57-C66 C69 C71-C73 C75-C77 C80 = rc-master:C_: NON-POLARIZED CAP
C3 C21 C26-C28 C55 C56 C67 C68 C70 C74 C78 C79 = rc-master:CP_: POLARIZED CAP
D1 = diode:DIODE-: DIODE
D2 D7 D8 D10 = diode:ZENER-DIODE: Z-Diode
D5 D6 D9 = diode:S1GB-13: RECTIFIER - (1N4004WDICT)
D11 = led:LED: LED
FIDUCIAL1-FIDUCIAL3 = dfiducial:FIDUCIAL-: FIDUCIAL MARKS
J1 = display-lcd:DMC20261: LCD DISPLAY Optrex, 20 characters x 2 Lines
J2 = con-lstb:MA10-2: PIN HEADER
JP1 = atmel:AVR-JTAG-10: AVR JTAG Debug/Programming Header
JP2 = atmel:AVR-ISP-6: AVR ISP-6 Serial Programming Header
JP4 = jumper:JP2E: JUMPER
JP5 = jumper:JP2Q: JUMPER
L1 = inductor-steward:CM1812: COMMON MODE FILTER 5A
L2 = rc-master:L_: INDUCTOR
L3 = rc-master:FB_: FERRITE BEAD
L4 = inductors-jwmiller:L: INDUCTORS
PF1 = fuse:POLYSWITCH: POLYSWITCH
Q1 Q5 = transistor-npn:MMBTA05: NPN TRANSISTOR
Q2 = zetex:ZXMN6A07Z: N-CHANNEL MOSFET
Q3 Q4 = transistor-fet:IRF614: N-Channel MOSFET (HEXFET) N-CHANNEL 250V 2.7A TO-220AB
R1 R3-R21 R23-R25 R28-R51 R53-R62 R64 R65 R67-R70 R72-R74 R76-R83 = rc-master:R_: RESISTOR
R2 R26 R27 R52 R63 R66 R71 R75 = pot:TRIM_EU-: POTENTIOMETER
R22 = ptc-ntc:NCP: NTC THERMISTOR
RN1 = resistor-array:744-8: CTS 744 Series 4 Resistors, 8 Terminations
S1 = switch:CK-A
TP1-TP7 TP9 = testpad:TP: TEST PIN
TP8 TP10 = testpoint:TPS: TEST POINT PAD
U1 = maxim:DS1307: Serial I2C Real Time Clock DALLAS Semiconductor
U2 = atmel:MEGA1281/2561: MICROCONTROLLER 128 Kbytes FLASH 8 Kbytes SRAM 4 Kbytes EEPROM
U3 = maxim:MAX3243*: RS-232 Transceivers with AutoShutdown 1µA Supply-Current, True +3V to +5.5V http://dbserv.maxim-ic.com/
U4 = v-reg:L78LXXCU/BU: VOLTAGE REGULATOR
U5 = linear:LM324: OP AMP
U6 = linear:CM8870C: CMOS Integrated DTMF Receiver cm8870.pdf
U7 = maxim:MAX323: ANALOG SWITCH
U8 = cml-micro:MX828: CTCSS/DCS/SELCALL PROCESSOR (OBSOLETE PART!)
U9 = isd:ISD4002: VOICE RECORD/PLAYBACK IC 3V, ISP Interface, 120-240 Second Duration
U10 = linear:TL084: OP AMP
U11 = v-reg:L78XX: VOLTAGE REGULATOR
U12 = v-reg:AD158X: VOLTAGE REFERENCE Precision a Series Mode Voltage References AD1582/AD1583/AD1584/AD1585
X1 = con-ost:EDSTLZ-2: ON-SHORE
X2 = con-subd:NC182M9-VS: SUB-D MALE - NorComp
X3 = con-hdrs40:HDR-1X8: HEADER CONNECTOR
X4 = con-amp:MTA08: AMP connector
X5 = con-hdrs40:HDR-1X2: HEADER CONNECTOR
Y1-Y4 = crystal:CRYTAL: CRYSTAL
